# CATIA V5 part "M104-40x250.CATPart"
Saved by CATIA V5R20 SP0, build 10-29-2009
Part number: M104-40x250
Source: Unknown
Bounding box of the stored display mesh (mm): x -19.994 to 19.994, y -19.994 to 19.994, z 0 to 250
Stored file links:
  C:\Users\Utente\Desktop\IO LAVORO\3D X SITO CF\X SITO\M104\M104-40x250.CATPart

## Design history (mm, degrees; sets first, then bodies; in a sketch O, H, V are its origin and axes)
Body1 (main body)
  Solid1 "PartBody": solid without history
